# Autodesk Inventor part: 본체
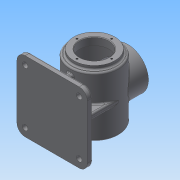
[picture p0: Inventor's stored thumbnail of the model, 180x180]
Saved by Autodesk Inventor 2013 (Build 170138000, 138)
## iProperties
Created: 2015-07
Part Number: 본체
Material: 일반
Document SubType Name: Modeling
Designer: Administrator
Density: 1 g/cm^3
Author: Administrator
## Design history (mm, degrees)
sketch "스케치1"
  geometry: C1 r 45 at (0, 0); 1 further point
  constraints: 1 centre point, 1 coincident
  dimensions: "d0" = 90 diameter of C1
extrude "돌출1" new body sketch "스케치1" stored distance "d1" = 110; taper "d2" = 0 deg
node "작업 평면1"
sketch "스케치2"
  geometry: C1 r 38 at (0, 0); 1 further point
  constraints: 1 centre point, 1 coincident
  dimensions: "d4" = 76 diameter of C1
extrude "돌출2" join sketch "스케치2" stored distance "d5" = 110; taper "d6" = 0 deg
node "작업 평면2"
sketch "스케치3"
  geometry: L1 (65, -65)-(-65, -65); L2 (-65, -65)-(-65, 65); L3 (-65, 65)-(65, 65); L4 (65, 65)-(65, -65); L5 (65, -65)-(-65, 65); L6 (-65, -65)-(65, 65); 1 further point
  constraints: 12 end point, 2 midpoint, 2 parallel, 1 horizontal, 1 perpendicular
  dimensions: "d8" = 130 distance of L1.end L2.end; "d10" = 130 distance of L2.end L3.end
extrude "돌출3" join sketch "스케치3" distance "d11" = 10; taper "d12" = 0 deg
sketch "스케치4"
  geometry: C1 r 45 at (0, 0) reference; C2 r 38 at (0, 0)
  constraints: 1 centre point, 1 coincident
  dimensions: "d13" = 76 diameter of C2
extrude "돌출4" join sketch "스케치4" distance "d14" = 7; taper "d15" = 0 deg
node "작업 평면3"
sketch "스케치5"
  geometry: C1 r 40 at (0, 0); 1 further point
  constraints: 1 centre point, 1 coincident
  dimensions: "d17" = 80 diameter of C1
extrude "돌출5" cut sketch "스케치5" distance "d18" = 96; taper "d19" = 0 deg
hole "구멍1" diameter "d22" = 54; stored, may be unused: countersink angle "d26" = 90 deg, drill point angle "d28" = 0 deg; dims "d20" = 10, "d21" = 10, "d23" = 6, "d24" = 4, "d25" = 2, "d27" = 14
hole "구멍2" diameter "d31" = 54; stored, may be unused: countersink angle "d35" = 90 deg, drill point angle "d37" = 0 deg; dims "d29" = 10, "d30" = 10, "d32" = 6, "d33" = 4, "d34" = 2, "d36" = 14
sketch "스케치6"
  geometry: C1 r 27 at (0, 0) reference; 1 further point
  constraints: 1 vertical alignment
  dimensions: "d38" = 32 distance of point (0, 32) C1.centre
hole "구멍3" sketch "스케치6" at (0, 32) diameter "d39" = 3.242; stored, may be unused: countersink angle "d43" = 90 deg, drill point angle "d45" = 118 deg; dims "d40" = 8, "d41" = 4, "d42" = 2, "d44" = 10
sketch "스케치7"
  geometry: C1 r 27 at (0, 0) reference; 1 further point
  constraints: 1 vertical alignment
  dimensions: "d49" = 32 distance of C1.centre point (0, 32)
hole "구멍4" sketch "스케치7" at (0, 32) diameter "d50" = 3.242; stored, may be unused: countersink angle "d54" = 90 deg, drill point angle "d56" = 118 deg; dims "d51" = 8, "d52" = 4, "d53" = 2, "d55" = 10
sketch "스케치8"
  geometry: L1 (-5, 45)-(5, 45); L2 (5, 45)-(5, -45); L3 (5, -45)-(-5, -45); L4 (-5, -45)-(-5, 45); L5 (-5, 45)-(5, -45); L6 (5, 45)-(-5, -45); L7 (-45, 5)-(45, 5); L8 (45, 5)-(45, -5); L9 (45, -5)-(-45, -5); L10 (-45, -5)-(-45, 5); L11 (-45, 5)-(45, -5); L12 (45, 5)-(-45, -5); 2 further points
  constraints: 24 end point, 4 midpoint, 4 parallel, 2 horizontal, 2 perpendicular, 1 coincident
  dimensions: "d62" = 90 distance of L1.end L2.end; "d64" = 90 distance of L7.start L7.end; "d65" = 10 distance between parallel lines of L4 L2; "d66" = 10 distance between parallel lines of L9 L7
extrude "돌출6" join sketch "스케치8" stored distance "d67" = 96; taper "d68" = 0 deg
sketch "스케치9"
  geometry: C1 r 7.5 at (50, -50); 1 further point
  constraints: 1 centre point
  dimensions: "d69" = 15 diameter of C1; "d71" = 50 horizontal distance of C1.centre point (0, 0); "d72" = 50 horizontal distance of point (0, 0) C1.centre
extrude "돌출7" join sketch "스케치9" distance "d73" = 3; taper "d74" = 0 deg
hole "구멍5" diameter "d77" = 10; stored, may be unused: countersink angle "d81" = 90 deg, drill point angle "d83" = 118 deg; dims "d75" = 10, "d76" = 10, "d78" = 8, "d79" = 4, "d80" = 2, "d82" = 10
fillet "모깎기1" dims "d87" = 3, "d88" = 15
fillet "모깎기2" dims "d89" = 3
chamfer "모따기1" distance "d90" = 1; stored, may be unused: second distance "d91" = 2, angle "d92" = 45 deg
sketch "스케치10"
  geometry: C1 r 42 at (0, 0) reference; 1 further point
  constraints: 1 coincident, 1 other
feature "엠보싱1" sketch "스케치10" dims "d13" = 76, "d93" = 0.5, "d94" = 0
node "솔리드1"
pattern_circular "원형 패턴1" dims angle "d47" = 360 deg
pattern_circular "원형 패턴2" dims angle "d58" = 360 deg
pattern_circular "원형 패턴3" dims angle "d85" = 360 deg
other parameters: "d3" = 62, "d7" = -78, "d16" = -7
